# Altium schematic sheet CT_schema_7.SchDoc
size 274 x 160 mm
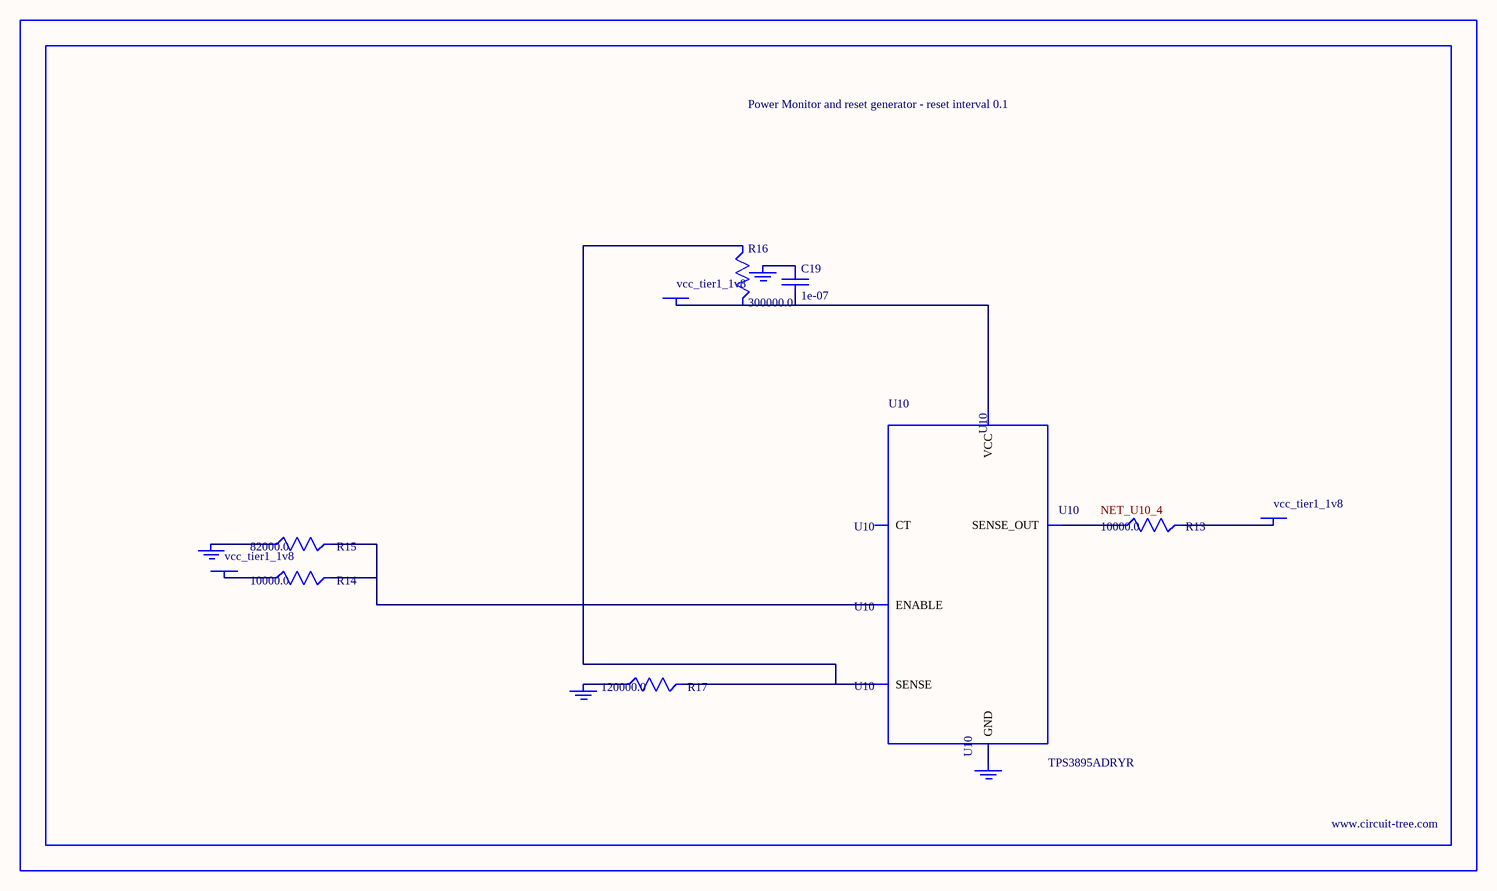
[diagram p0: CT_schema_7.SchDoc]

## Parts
BORDER6  (no value)
C19  1e-07  [C0402]
GND_INSTANCE_6_0  (no value)
GND_INSTANCE_6_1  (no value)
GND_INSTANCE_6_2  (no value)
GND_INSTANCE_6_3  (no value)
POWER_INSTANCE_6_0  vcc_tier1_1v8
POWER_INSTANCE_6_1  vcc_tier1_1v8
POWER_INSTANCE_6_2  vcc_tier1_1v8
R13  10000.0  [R0603]
R14  10000.0  [R0603]
R15  82000.0  [R0603]
R16  300000.0  [R0603]
R17  120000.0  [R0603]
U10  TPS3895ADRYR  [SON-6]

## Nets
NetC19_1: C19.1 GND_INSTANCE_6_2.0(GND)
NetC19_2: C19.2 POWER_INSTANCE_6_2.0(PWR) R16.2 U10.6(VCC)
NetGND_INSTANCE_6_0_0: GND_INSTANCE_6_0.0(GND) R15.1
NetGND_INSTANCE_6_1_0: GND_INSTANCE_6_1.0(GND) R17.1
NetGND_INSTANCE_6_3_0: GND_INSTANCE_6_3.0(GND) U10.2(GND)
NetPOWER_INSTANCE_6_0_0: POWER_INSTANCE_6_0.0(PWR) R14.1
NetPOWER_INSTANCE_6_1_0: POWER_INSTANCE_6_1.0(PWR) R13.2
NetR13_1: R13.1 U10.4(SENSE_OUT)
NetR14_2: R14.2 R15.2 U10.1(ENABLE)
NetR16_1: R16.1 R17.2 U10.3(SENSE)

Not connected (* = marked no-connect by the designer): U10 5(CT)

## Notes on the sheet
- Labels drawn without touching a wire or pin: NET_U10_4

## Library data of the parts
BORDER6 = BORDER_PAGE6
C19 = C0402C104K3RACTU
GND_INSTANCE_6_0-GND_INSTANCE_6_3 = GND
POWER_INSTANCE_6_0-POWER_INSTANCE_6_2 = PWR
R13 R14 = RC0603JR-0710KL
R15 = RC0603JR-0782KL
R16 = RC0603JR-07300KL
R17 = RC0603JR-07120KL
